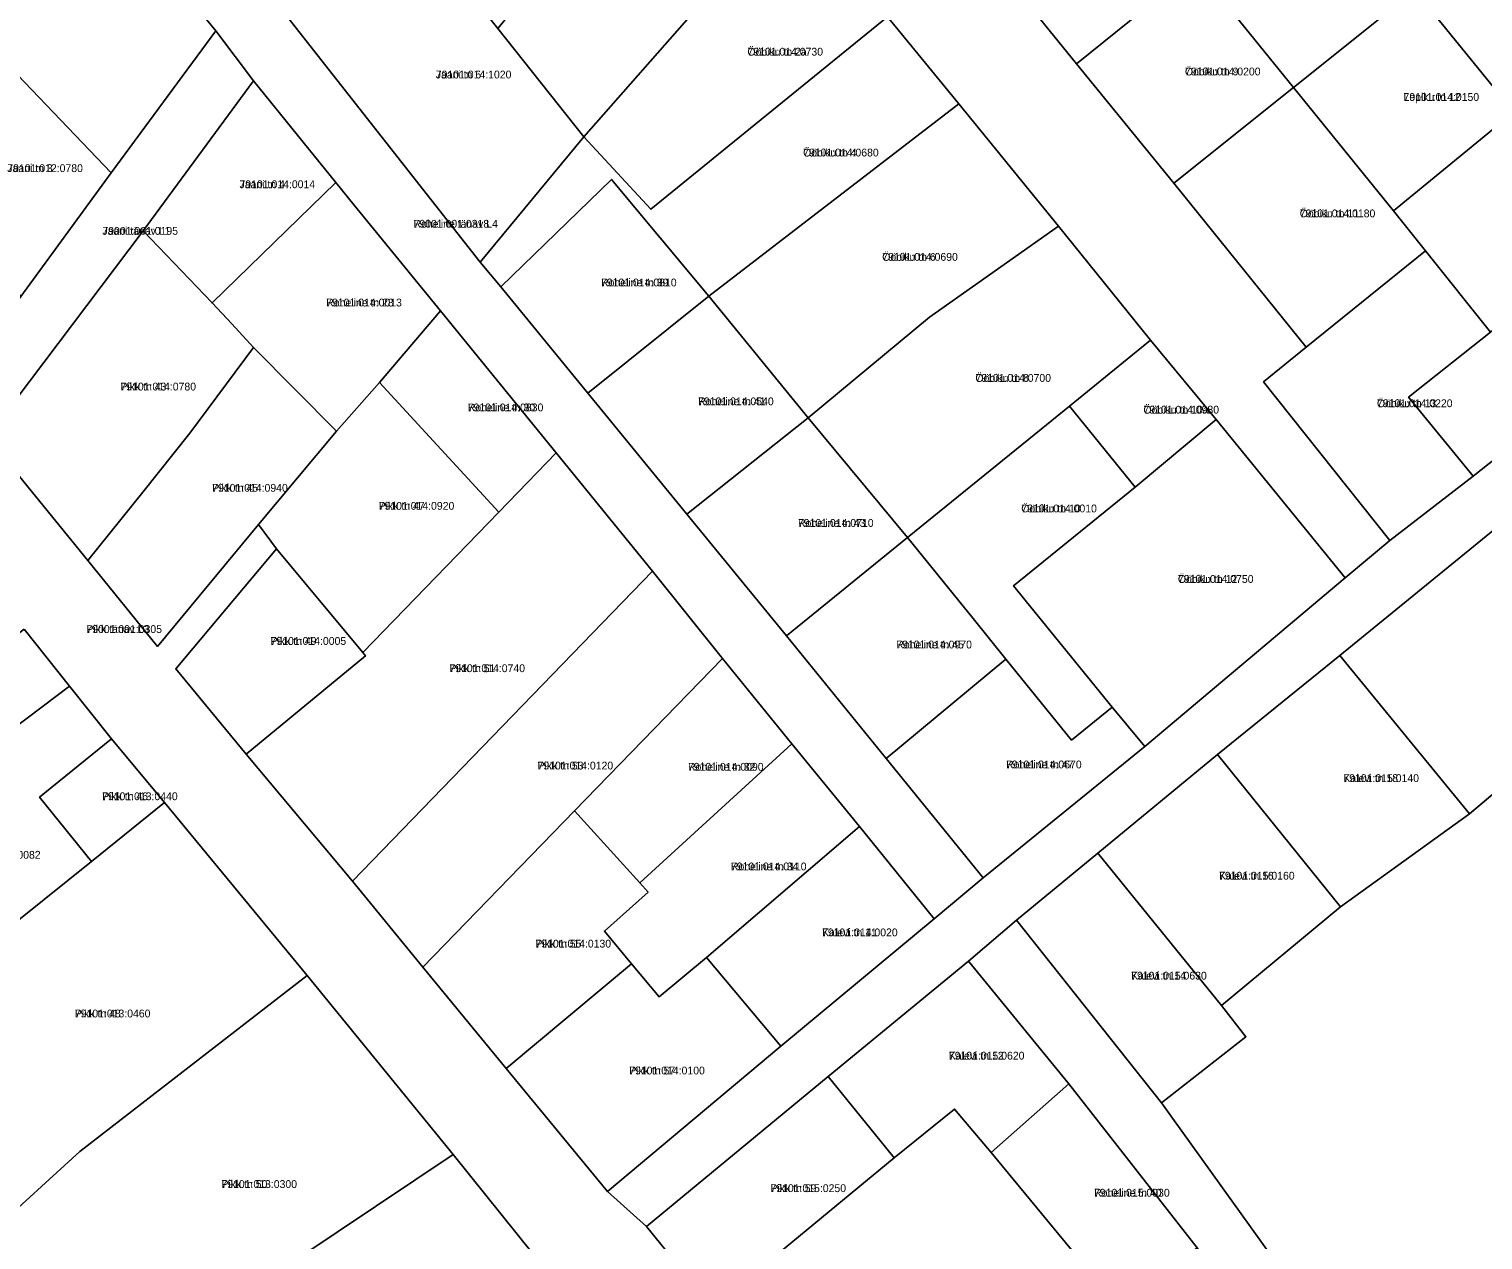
# Model space of a CAD drawing. Extents: x 587616 to 632239, y 6547421 to 6574977.
# Drawn here: x 612323.4 to 612602.3, y 6570318.2 to 6570550.5 of the extents above; entities that cross this region are included whole.
import ezdxf

# ---------------------------------------------------------------- set-up
doc = ezdxf.new("R2010")
doc.units = 0
for name, color, linetype in [('L_AADRESS', 7, 'Continuous'), ('PIIR', 7, 'Continuous'), ('TUNNUS', 7, 'Continuous')]:
    doc.layers.add(name, color=color, linetype=linetype)

msp = doc.modelspace()

# ---------------------------------------------------------------- linework, layer by layer
at = {"layer": 'PIIR'}
for points in [[(612639.61, 6570495.79), (612627.14, 6570511.23), (612608.16, 6570534.51), (612589.19, 6570557.93), (612570.4, 6570581.47), (612551.7, 6570604.82), (612530.58, 6570630.22), (612522.61, 6570640.4), (612505.68, 6570653.17), (612471.53, 6570678.85), (612478.97, 6570688.58), (612499.31, 6570673.44), (612528.11, 6570648.18), (612538.11, 6570640.38), (612568.81, 6570602.35), (612580.82, 6570587.48), (612602.49, 6570560.97), (612615.08, 6570545.35), (612627.71, 6570530.02), (612649.48, 6570503.22)], [(612447.92, 6570593.85), (612422.16, 6570613.6), (612437.77, 6570634.29), (612463.51, 6570615.22), (612483.01, 6570595.16), (612505.23, 6570567.34), (612524.3, 6570543.79), (612542.99, 6570520.86), (612568.33, 6570489.4), (612560.18, 6570482.76), (612584.42, 6570452.32), (612575.81, 6570445.21), (612551.11, 6570475.57), (612538.51, 6570490.8), (612520.83, 6570512.64), (612501.76, 6570536.12), (612488.02, 6570552.83), (612469.38, 6570574.82), (612450.44, 6570597.17)], [(612339.15, 6570522.88), (612312.79, 6570550.34), (612295.67, 6570565.84), (612320.6, 6570597.07), (612359.19, 6570550.12)], [(612413.31, 6570550.56), (612436.57, 6570579.17), (612447.92, 6570593.85), (612450.44, 6570597.17), (612469.38, 6570574.82), (612429.81, 6570529.75)], [(612505.23, 6570567.34), (612528, 6570586.24), (612547.26, 6570562.3), (612524.3, 6570543.79)], [(612570.4, 6570581.47), (612589.19, 6570557.93), (612565.91, 6570539.27), (612547.26, 6570562.3)], [(612391.73, 6570577.49), (612413.31, 6570550.56), (612429.81, 6570529.75), (612409.94, 6570505.71), (612373.01, 6570552.66)], [(612429.81, 6570529.75), (612469.38, 6570574.82), (612488.02, 6570552.83), (612442.67, 6570515.9)], [(612524.3, 6570543.79), (612547.26, 6570562.3), (612565.91, 6570539.27), (612542.99, 6570520.86)], [(612565.91, 6570539.27), (612589.19, 6570557.93), (612608.16, 6570534.51), (612585.12, 6570515.56)], [(612309.05, 6570524.33), (612303.9, 6570528.27), (612299.3, 6570531.87), (612312.79, 6570550.34), (612339.15, 6570522.88), (612321.82, 6570499.15), (612305.1, 6570520.14)], [(612453.81, 6570499.2), (612435.1, 6570521.61), (612413.89, 6570501.02), (612409.94, 6570505.71), (612429.81, 6570529.75), (612442.67, 6570515.9), (612488.02, 6570552.83), (612501.76, 6570536.12)], [(612308.47, 6570480.33), (612321.82, 6570499.15), (612339.15, 6570522.88), (612359.19, 6570550.12), (612366.46, 6570540.5), (612345.29, 6570511.76), (612315.37, 6570472.15)], [(612366.46, 6570540.5), (612382.23, 6570520.99), (612358.51, 6570497.93), (612345.29, 6570511.76)], [(612565.91, 6570539.27), (612585.12, 6570515.56), (612591.25, 6570507.93), (612568.33, 6570489.4), (612542.99, 6570520.86)], [(612453.81, 6570499.2), (612501.76, 6570536.12), (612520.83, 6570512.64), (612496.1, 6570495.17), (612472.84, 6570475.88)], [(612627.14, 6570511.23), (612603.69, 6570492.34), (612591.25, 6570507.93), (612585.12, 6570515.56), (612608.16, 6570534.51)], [(612382.23, 6570520.99), (612385.75, 6570516.7), (612402.3, 6570496.37), (612390.6, 6570482.65), (612382.35, 6570473.29), (612366.47, 6570489.39), (612362.26, 6570493.89), (612358.51, 6570497.93)], [(612413.89, 6570501.02), (612435.1, 6570521.61), (612453.81, 6570499.2), (612430.6, 6570480.58)], [(612315.37, 6570472.15), (612345.29, 6570511.76), (612358.51, 6570497.93), (612362.26, 6570493.89), (612366.47, 6570489.39), (612354.23, 6570472.93), (612345.23, 6570461.63), (612334.69, 6570448.49)], [(612472.84, 6570475.88), (612496.1, 6570495.17), (612520.83, 6570512.64), (612538.51, 6570490.8), (612522.94, 6570478.1), (612515.18, 6570471.8), (612491.88, 6570452.91)], [(612588, 6570479.83), (612603.69, 6570492.34), (612627.14, 6570511.23), (612639.61, 6570495.79), (612600.41, 6570464.66)], [(612568.33, 6570489.4), (612591.25, 6570507.93), (612603.69, 6570492.34), (612588, 6570479.83), (612600.41, 6570464.66), (612584.42, 6570452.32), (612560.18, 6570482.76)], [(612453.81, 6570499.2), (612472.84, 6570475.88), (612449.59, 6570457.37), (612430.6, 6570480.58)], [(612402.3, 6570496.37), (612424.48, 6570469.13), (612413.53, 6570457.81), (612390.6, 6570482.65)], [(612334.69, 6570448.49), (612345.23, 6570461.63), (612354.23, 6570472.93), (612366.47, 6570489.39), (612382.35, 6570473.29), (612367.4, 6570455.41), (612348, 6570432.02)], [(612522.94, 6570478.1), (612538.51, 6570490.8), (612551.11, 6570475.57), (612535.53, 6570462.57)], [(612367.4, 6570455.41), (612382.35, 6570473.29), (612390.6, 6570482.65), (612413.53, 6570457.81), (612387.43, 6570430.85), (612370.83, 6570450.73)], [(612523.37, 6570414.07), (612510.77, 6570429.6), (612504.48, 6570437.38), (612491.88, 6570452.91), (612515.18, 6570471.8), (612522.94, 6570478.1), (612535.53, 6570462.57), (612512.23, 6570443.67), (612531.14, 6570420.38)], [(612449.59, 6570457.37), (612472.84, 6570475.88), (612491.88, 6570452.91), (612468.7, 6570434.03)], [(612531.14, 6570420.38), (612512.23, 6570443.67), (612535.53, 6570462.57), (612551.11, 6570475.57), (612575.81, 6570445.21), (612537.42, 6570412.85)], [(612365.05, 6570411.38), (612387.91, 6570430.19), (612387.43, 6570430.85), (612413.53, 6570457.81), (612424.48, 6570469.13), (612442.99, 6570446.46), (612385.42, 6570386.98)], [(612599.66, 6570399.92), (612574.83, 6570430.3), (612607.05, 6570456.59), (612626.26, 6570432.96), (612631.54, 6570426.71)], [(612468.7, 6570434.03), (612491.88, 6570452.91), (612504.48, 6570437.38), (612510.77, 6570429.6), (612487.82, 6570410.53)], [(612370.83, 6570450.73), (612387.43, 6570430.85), (612387.91, 6570430.19), (612365.05, 6570411.38), (612351.54, 6570427.74)], [(612385.42, 6570386.98), (612442.99, 6570446.46), (612456.43, 6570429.69), (612428.02, 6570400.5), (612398.92, 6570370.48)], [(612322.44, 6570435.33), (612331.16, 6570424.37), (612279.74, 6570385.58), (612273.18, 6570397.81)], [(612440.55, 6570386.66), (612428.02, 6570400.5), (612456.43, 6570429.69), (612469.71, 6570413.34)], [(612487.82, 6570410.53), (612510.77, 6570429.6), (612523.37, 6570414.07), (612531.14, 6570420.38), (612537.42, 6570412.85), (612506.38, 6570387.66)], [(612574.83, 6570430.3), (612599.66, 6570399.92), (612574.91, 6570382.1), (612551.32, 6570411.28)], [(612331.16, 6570424.37), (612339.18, 6570414.32), (612325.4, 6570403.08), (612335.35, 6570390.74), (612294.75, 6570358.23), (612285.37, 6570374.87), (612279.74, 6570385.58)], [(612325.4, 6570403.08), (612339.18, 6570414.32), (612349.34, 6570402.06), (612335.35, 6570390.74)], [(612540.6, 6570344.47), (612556.79, 6570357.16), (612552.1, 6570363.13), (612574.91, 6570382.1), (612599.66, 6570399.92), (612619.27, 6570416.4), (612715.08, 6570284.4), (612629.38, 6570221.01), (612569.4, 6570304.36)], [(612444.25, 6570364.81), (612438.97, 6570371.12), (612433.75, 6570377.41), (612442.13, 6570384.89), (612440.55, 6570386.66), (612469.71, 6570413.34), (612482.71, 6570397.51), (612453.31, 6570372.38)], [(612551.32, 6570411.28), (612574.91, 6570382.1), (612552.1, 6570363.13), (612528.37, 6570392.35)], [(612316.12, 6570319.66), (612304.52, 6570340.49), (612294.75, 6570358.23), (612335.35, 6570390.74), (612349.34, 6570402.06), (612376.72, 6570368.9), (612333.12, 6570335.16)], [(612398.92, 6570370.48), (612428.02, 6570400.5), (612440.55, 6570386.66), (612442.13, 6570384.89), (612433.75, 6570377.41), (612438.97, 6570371.12), (612414.92, 6570351.07)], [(612453.31, 6570372.38), (612482.71, 6570397.51), (612496.97, 6570379.74), (612467.59, 6570355.32)], [(612528.37, 6570392.35), (612552.1, 6570363.13), (612556.79, 6570357.16), (612540.6, 6570344.47), (612512.79, 6570379.53)], [(612512.79, 6570379.53), (612540.6, 6570344.47), (612569.4, 6570304.36), (612629.38, 6570221.01), (612653.67, 6570187.98), (612589.97, 6570141.86), (612563.02, 6570172.78), (612595.67, 6570193.13), (612622.46, 6570209.79), (612591.43, 6570253.85), (612569.06, 6570283.13), (612547.43, 6570316.69), (612522.81, 6570348.13), (612503.56, 6570371.63)], [(612414.92, 6570351.07), (612438.97, 6570371.12), (612444.25, 6570364.81), (612453.31, 6570372.38), (612467.59, 6570355.32), (612434.35, 6570327.46)], [(612503.56, 6570371.63), (612522.81, 6570348.13), (612507.92, 6570334.92), (612500.93, 6570343.26), (612489.3, 6570333.91), (612476.67, 6570349.52)], [(612334.23, 6570287.38), (612316.12, 6570319.66), (612333.12, 6570335.16), (612376.72, 6570368.9), (612404.74, 6570334.54), (612375.14, 6570314.75), (612346.68, 6570295.76)], [(612489.3, 6570333.91), (612454.48, 6570305.18), (612441.83, 6570320.73), (612476.67, 6570349.52)], [(612522.81, 6570348.13), (612547.43, 6570316.69), (612533.02, 6570304.57), (612507.92, 6570334.92)], [(612500.93, 6570343.26), (612507.92, 6570334.92), (612533.02, 6570304.57), (612524.57, 6570297.67), (612520.43, 6570302.8), (612482.38, 6570272.08), (612454.48, 6570305.18), (612489.3, 6570333.91)], [(612404.74, 6570334.54), (612420.14, 6570315.41), (612389.85, 6570294.04), (612375.14, 6570314.75)]]:
    msp.add_lwpolyline(points, close=True, dxfattribs=at)
for points in [[(612321.39, 6570614.7), (612342.43, 6570588.6), (612366.02, 6570559.5), (612373.01, 6570552.66), (612409.94, 6570505.71), (612413.89, 6570501.02), (612430.6, 6570480.58), (612449.59, 6570457.37), (612468.7, 6570434.03), (612487.82, 6570410.53), (612506.38, 6570387.66), (612496.97, 6570379.74), (612482.71, 6570397.51), (612469.71, 6570413.34), (612456.43, 6570429.69), (612442.99, 6570446.46), (612424.48, 6570469.13), (612402.3, 6570496.37), (612385.75, 6570516.7), (612382.23, 6570520.99), (612366.46, 6570540.5), (612359.19, 6570550.12), (612320.6, 6570597.07)], [(612607.05, 6570456.59), (612574.83, 6570430.3), (612551.32, 6570411.28), (612528.37, 6570392.35), (612512.79, 6570379.53), (612503.56, 6570371.63), (612476.67, 6570349.52), (612441.83, 6570320.73), (612434.35, 6570327.46), (612467.59, 6570355.32), (612496.97, 6570379.74), (612506.38, 6570387.66), (612537.42, 6570412.85), (612575.81, 6570445.21), (612584.42, 6570452.32), (612600.41, 6570464.66), (612639.61, 6570495.79)], [(612315.37, 6570472.15), (612334.69, 6570448.49), (612348, 6570432.02), (612367.4, 6570455.41), (612370.83, 6570450.73), (612351.54, 6570427.74), (612365.05, 6570411.38), (612385.42, 6570386.98), (612398.92, 6570370.48), (612414.92, 6570351.07), (612434.35, 6570327.46), (612441.83, 6570320.73), (612454.48, 6570305.18)], [(612420.14, 6570315.41), (612404.74, 6570334.54), (612376.72, 6570368.9), (612349.34, 6570402.06), (612339.18, 6570414.32), (612331.16, 6570424.37), (612322.44, 6570435.33)]]:
    msp.add_lwpolyline(points, dxfattribs=at)

# ---------------------------------------------------------------- texts
at = {"layer": 'L_AADRESS'}
for s, p in [('Ööbiku tn 2a', (612461.18, 6570545.36)), ('Jaani tn 6', (612401.41, 6570540.98)), ('Ööbiku tn 9', (612545.1, 6570541.56)), ('Lepiku tn 12', (612587.03, 6570536.67)), ('Ööbiku tn 4', (612471.86, 6570526.01)), ('Jaani tn 3', (612319.22, 6570523.02)), ('Jaani tn 4', (612363.76, 6570519.93)), ('Ööbiku tn 11', (612567.12, 6570514.34)), ('Jaani tänav L1', (612337.46, 6570510.99)), ('Roheline tänav L4', (612397.14, 6570512.35)), ('Ööbiku tn 6', (612487.04, 6570506)), ('Roheline tn 39', (612433.1, 6570501.09)), ('Roheline tn 28', (612380.4, 6570497.24)), ('Ööbiku tn 8', (612504.91, 6570482.78)), ('Pikk tn 43', (612340.92, 6570481.12)), ('Roheline tn 30', (612407.54, 6570477.12)), ('Roheline tn 41', (612451.72, 6570478.29)), ('Ööbiku tn 10a', (612537.14, 6570476.69)), ('Ööbiku tn 13', (612581.93, 6570477.92)), ('Pikk tn 45', (612358.52, 6570461.7)), ('Pikk tn 47', (612390.46, 6570458.24)), ('Ööbiku tn 10', (612513.71, 6570457.74)), ('Roheline tn 43', (612470.88, 6570454.96)), ('Ööbiku tn 12', (612543.76, 6570444.21)), ('Pikk tänav L3', (612334.39, 6570434.6)), ('Pikk tn 49', (612369.72, 6570432.32)), ('Roheline tn 45', (612489.74, 6570431.64)), ('Pikk tn 51', (612404.02, 6570427.09)), ('Pikk tn 53', (612420.93, 6570408.42)), ('Roheline tn 32', (612449.78, 6570408.18)), ('Roheline tn 47', (612510.79, 6570408.63)), ('Kalevi tn 18', (612575.49, 6570406.01)), ('Pikk tn 46', (612337.4, 6570402.53)), ('Roheline tn 34', (612458.02, 6570389.07)), ('Kalevi tn 16', (612551.64, 6570387.29)), ('Kalevi tn 11', (612475.5, 6570376.42)), ('Pikk tn 55', (612420.53, 6570374.26)), ('Kalevi tn 14', (612534.79, 6570368.12)), ('Pikk tn 48', (612332.18, 6570360.86)), ('Kalevi tn 12', (612499.82, 6570352.77)), ('Pikk tn 57', (612438.51, 6570349.92)), ('Pikk tn 50', (612360.29, 6570328.14)), ('Pikk tn 59', (612465.6, 6570327.35)), ('Roheline tn 40', (612527.68, 6570326.48))]:
    msp.add_text(s, height=1.5, dxfattribs=at).set_placement(p)
at = {"layer": 'TUNNUS'}
for s, p in [('79101:014:0730', (612461.18, 6570545.36)), ('79101:014:1020', (612401.41, 6570540.98)), ('79101:014:0200', (612545.1, 6570541.56)), ('79101:014:0150', (612587.03, 6570536.67)), ('79101:014:0680', (612471.86, 6570526.01)), ('79101:012:0780', (612319.22, 6570523.02)), ('79101:014:0014', (612363.76, 6570519.93)), ('79101:014:0180', (612567.12, 6570514.34)), ('79001:001:0195', (612337.46, 6570510.99)), ('79001:001:0318', (612397.14, 6570512.35)), ('79101:014:0690', (612487.04, 6570506)), ('79101:014:0810', (612433.1, 6570501.09)), ('79101:014:0013', (612380.4, 6570497.24)), ('79101:014:0700', (612504.91, 6570482.78)), ('79101:014:0780', (612340.92, 6570481.12)), ('79101:014:0830', (612407.54, 6570477.12)), ('79101:014:0540', (612451.72, 6570478.29)), ('79101:014:0980', (612537.14, 6570476.69)), ('79101:014:0220', (612581.93, 6570477.92)), ('79101:014:0940', (612358.52, 6570461.7)), ('79101:014:0920', (612390.46, 6570458.24)), ('79101:014:0010', (612513.71, 6570457.74)), ('79101:014:0710', (612470.88, 6570454.96)), ('79101:014:0750', (612543.76, 6570444.21)), ('79001:001:0305', (612334.39, 6570434.6)), ('79101:014:0005', (612369.72, 6570432.32)), ('79101:014:0970', (612489.74, 6570431.64)), ('79101:014:0740', (612404.02, 6570427.09)), ('79101:014:0120', (612420.93, 6570408.42)), ('79101:014:0090', (612449.78, 6570408.18)), ('79101:014:0670', (612510.79, 6570408.63)), ('79101:015:0140', (612575.49, 6570406.01)), ('79101:013:0440', (612337.4, 6570402.53)), ('79101:013:0082', (612311.11, 6570391.3)), ('79101:014:0110', (612458.02, 6570389.07)), ('79101:015:0160', (612551.64, 6570387.29)), ('79101:014:0020', (612475.5, 6570376.42)), ('79101:014:0130', (612420.53, 6570374.26)), ('79101:015:0630', (612534.79, 6570368.12)), ('79101:013:0460', (612332.18, 6570360.86)), ('79101:015:0620', (612499.82, 6570352.77)), ('79101:014:0100', (612438.51, 6570349.92)), ('79101:013:0300', (612360.29, 6570328.14)), ('79101:015:0250', (612465.6, 6570327.35)), ('79101:015:0030', (612527.68, 6570326.48))]:
    msp.add_text(s, height=1.5, dxfattribs=at).set_placement(p)

doc.saveas('drawing.dxf')
